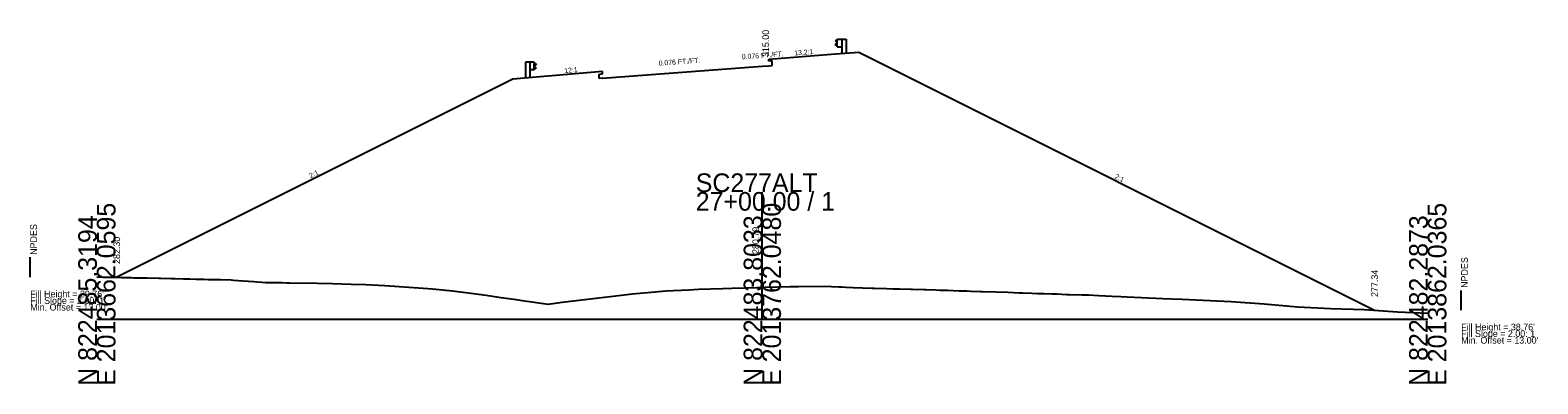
# Model space of a CAD drawing. Extents: x 205929 to 2357175, y -1785700 to 827636.
# Drawn here: x 2017410.1 to 2017636.7, y 825034.6 to 825087.7 of the extents above; entities that cross this region are included whole.
import ezdxf

# ---------------------------------------------------------------- set-up
doc = ezdxf.new("R2010")
doc.units = 0
for name, color, linetype in [('RD_GPK_XS_Cell', 7, 'Continuous'), ('RD_XS_Base', 7, 'Continuous'), ('RD_XS_EarthShd', 7, 'Continuous'), ('RD_XS_ExGround', 7, 'Continuous'), ('RD_XS_GR', 7, 'Continuous'), ('RD_XS_NPDES', 7, 'Continuous'), ('RD_XS_Pave', 7, 'Continuous'), ('RD_XS_TieSlope', 7, 'Continuous'), ('RD_XS_TX_Elev_EX', 7, 'Continuous'), ('RD_XS_TX_Elev_PR', 7, 'Continuous'), ('RD_XS_TX_ShdSlope', 7, 'Continuous'), ('RD_XS_TX_Slope', 7, 'Continuous'), ('RD_XS_TX_Warning', 7, 'Continuous')]:
    doc.layers.add(name, color=color, linetype=linetype)

msp = doc.modelspace()

# ---------------------------------------------------------------- linework, layer by layer
at = {"layer": 'RD_GPK_XS_Cell'}
for p, q in [((2017520.17, 825044.26), (2017520.17, 825063.36)), ((2017420.17, 825044.26), (2017520.17, 825044.26)), ((2017520.17, 825044.26), (2017620.17, 825044.26))]:
    msp.add_line(p, q, dxfattribs=at)
at = {"layer": 'RD_XS_Base'}
for p, q in [((2017496.17, 825080.44), (2017520.17, 825082.26)), ((2017520.17, 825082.26), (2017521.17, 825082.33))]:
    msp.add_line(p, q, dxfattribs=at)
at = {"layer": 'RD_XS_EarthShd'}
for p, q in [((2017521.17, 825083.33), (2017531.17, 825084.09)), ((2017531.17, 825084.09), (2017534.67, 825084.36)), ((2017496.17, 825081.44), (2017486.17, 825080.6)), ((2017486.17, 825080.6), (2017482.67, 825080.31))]:
    msp.add_line(p, q, dxfattribs=at)
at = {"layer": 'RD_XS_ExGround'}
msp.add_lwpolyline([(2017420.17, 825050.62), (2017421.07, 825050.6), (2017421.98, 825050.57), (2017423.24, 825050.56), (2017423.85, 825050.54), (2017425.4, 825050.51), (2017425.72, 825050.5), (2017427.72, 825050.46), (2017429.46, 825050.42), (2017429.77, 825050.41), (2017431.32, 825050.38), (2017431.95, 825050.36), (2017433.19, 825050.34), (2017434.13, 825050.32), (2017435.05, 825050.3), (2017436.32, 825050.27), (2017436.91, 825050.25), (2017438.77, 825050.21), (2017440.33, 825050.18), (2017440.7, 825050.15), (2017442.17, 825050.03), (2017442.98, 825049.97), (2017443.76, 825049.91), (2017445.55, 825049.8), (2017446.99, 825049.79), (2017448.02, 825049.78), (2017448.7, 825049.75), (2017449.18, 825049.75), (2017453.29, 825049.7), (2017455.6, 825049.62), (2017458.37, 825049.52), (2017460.6, 825049.46), (2017463.44, 825049.31), (2017465.6, 825049.17), (2017468.52, 825048.97), (2017470.6, 825048.81), (2017473.6, 825048.52), (2017475.6, 825048.29), (2017478.68, 825047.87), (2017480.6, 825047.58), (2017483.18, 825047.23), (2017484.06, 825047.1), (2017485.53, 825046.88), (2017487.98, 825046.52), (2017490.1, 825046.83), (2017495.6, 825047.48), (2017498.99, 825047.88), (2017500.6, 825048.06), (2017504.07, 825048.4), (2017505.6, 825048.51), (2017509.14, 825048.69), (2017510.6, 825048.78), (2017514.22, 825048.89), (2017515.6, 825048.93), (2017519.3, 825049.03), (2017520.17, 825049.05), (2017520.6, 825049.06), (2017524.38, 825049.17), (2017525.61, 825049.19), (2017529.45, 825049.21), (2017531.69, 825049.14), (2017532.08, 825049.12), (2017532.7, 825049.09), (2017533.83, 825049.04), (2017536.65, 825048.92), (2017537.01, 825048.91), (2017538.83, 825048.86), (2017539.85, 825048.85), (2017540.78, 825048.83), (2017542.44, 825048.8), (2017542.76, 825048.79), (2017544.47, 825048.74), (2017544.79, 825048.73), (2017546.23, 825048.67), (2017546.83, 825048.65), (2017547.98, 825048.61), (2017548.86, 825048.58), (2017549.75, 825048.55), (2017550.9, 825048.52), (2017551.5, 825048.5), (2017552.94, 825048.44), (2017553.26, 825048.43), (2017555.28, 825048.37), (2017557.13, 825048.31), (2017558.78, 825048.25), (2017559.33, 825048.23), (2017560.67, 825048.17), (2017561.51, 825048.15), (2017562.54, 825048.11), (2017563.69, 825048.09), (2017564.43, 825048.07), (2017565.88, 825048), (2017566.32, 825047.99), (2017568.21, 825047.94), (2017569.18, 825047.92), (2017570.72, 825047.84), (2017572.74, 825047.73), (2017574.07, 825047.68), (2017575.01, 825047.63), (2017580.36, 825047.38), (2017581.69, 825047.31), (2017583.28, 825047.26), (2017590.61, 825046.94), (2017595.61, 825046.56), (2017600.61, 825046.13), (2017605.61, 825045.89), (2017610.62, 825045.7), (2017615.62, 825045.36), (2017620.17, 825045.15)], dxfattribs=at)
at = {"layer": 'RD_XS_GR'}
for p, q in [((2017531.44, 825086.27), (2017531.17, 825086.07)), ((2017531.17, 825086.07), (2017531.17, 825086.02)), ((2017531.17, 825086.02), (2017531.44, 825085.82)), ((2017531.17, 825085.5), (2017531.44, 825085.7)), ((2017531.17, 825085.45), (2017531.17, 825085.5)), ((2017531.44, 825085.17), (2017531.44, 825086.34)), ((2017531.44, 825086.34), (2017532.11, 825086.34)), ((2017532.11, 825086.34), (2017532.11, 825084.16)), ((2017532.11, 825086.34), (2017532.78, 825086.34)), ((2017532.78, 825086.34), (2017532.78, 825084.21)), ((2017531.44, 825085.25), (2017531.17, 825085.45)), ((2017531.44, 825085.17), (2017532.11, 825085.17)), ((2017484.57, 825082.85), (2017484.57, 825080.47)), ((2017485.24, 825082.85), (2017484.57, 825082.85)), ((2017485.24, 825082.85), (2017485.24, 825080.53)), ((2017485.9, 825082.85), (2017485.24, 825082.85)), ((2017485.9, 825081.69), (2017485.24, 825081.69)), ((2017485.9, 825081.69), (2017485.9, 825082.85)), ((2017485.9, 825082.78), (2017486.17, 825082.58)), ((2017486.17, 825082.53), (2017485.9, 825082.33)), ((2017486.17, 825082.01), (2017485.9, 825082.21)), ((2017485.9, 825081.76), (2017486.17, 825081.96)), ((2017486.17, 825082.58), (2017486.17, 825082.53)), ((2017486.17, 825081.96), (2017486.17, 825082.01))]:
    msp.add_line(p, q, dxfattribs=at)
at = {"layer": 'RD_XS_NPDES'}
for p, q in [((2017410.16, 825050.56), (2017410.16, 825053.56)), ((2017625.19, 825045.6), (2017625.19, 825048.6))]:
    msp.add_line(p, q, dxfattribs=at)
at = {"layer": 'RD_XS_Pave'}
for p, q in [((2017521.17, 825083), (2017521.17, 825083.33)), ((2017495.67, 825081.07), (2017496.17, 825081.11)), ((2017495.67, 825080.4), (2017495.67, 825081.07)), ((2017496.17, 825081.11), (2017496.17, 825081.44)), ((2017521.67, 825083.04), (2017521.17, 825083)), ((2017521.17, 825082.33), (2017521.67, 825082.37)), ((2017521.67, 825082.37), (2017521.67, 825083.04)), ((2017496.17, 825080.44), (2017495.67, 825080.4))]:
    msp.add_line(p, q, dxfattribs=at)
at = {"layer": 'RD_XS_TieSlope'}
for p, q in [((2017534.67, 825084.36), (2017612.19, 825045.6)), ((2017482.67, 825080.31), (2017423.16, 825050.56))]:
    msp.add_line(p, q, dxfattribs=at)

# ---------------------------------------------------------------- texts
at = {"layer": 'RD_GPK_XS_Cell'}
for s, p in [('SC277ALT', (2017510.17, 825063.36)), ('27+00.00 / 1', (2017510.17, 825060.56))]:
    msp.add_text(s, height=2.8, dxfattribs=at).set_placement(p)
for s, p in [('E 2013662.0595', (2017422.97, 825034.26)), ('E 2013762.0480', (2017522.97, 825034.26)), ('E 2013862.0365', (2017622.97, 825034.26)), ('N 822485.3194', (2017420.17, 825034.26)), ('N 822483.8033', (2017520.17, 825034.26)), ('N 822482.2873', (2017620.17, 825034.26))]:
    msp.add_text(s, height=2.8, rotation=90, dxfattribs=at).set_placement(p)
at = {"layer": 'RD_XS_TX_Elev_EX'}
msp.add_text('280.79', height=1, rotation=90, dxfattribs=at).set_placement((2017519.67, 825054.05))
at = {"layer": 'RD_XS_TX_Elev_PR'}
for s, p in [(' 315.00', (2017521.17, 825083.26)), ('282.30', (2017423.66, 825052.56)), ('277.34', (2017612.69, 825047.6))]:
    msp.add_text(s, height=1, rotation=90, dxfattribs=at).set_placement(p)
at = {"layer": 'RD_XS_TX_ShdSlope'}
for s, rotation, p in [('13.2:1', 4.3347, (2017525, 825083.87)), ('12:1', 4.7636, (2017490.44, 825081.21))]:
    msp.add_text(s, height=0.75, rotation=rotation, dxfattribs=at).set_placement(p)
at = {"layer": 'RD_XS_TX_Slope'}
for s, rotation, p in [('0.076 FT./FT.', 4.3347, (2017504.62, 825082.33)), ('0.076 FT./FT.', 4.3347, (2017517.12, 825083.28)), ('2:1', 26.5651, (2017452.3, 825065.41)), ('2:1', 333.4349, (2017573.04, 825065.45))]:
    msp.add_text(s, height=0.75, rotation=rotation, dxfattribs=at).set_placement(p)
at = {"layer": 'RD_XS_TX_Warning'}
for p in [(2017411.16, 825053.56), (2017626.19, 825048.6)]:
    msp.add_text(' NPDES', height=1, rotation=90, dxfattribs=at).set_placement(p)
for s, p in [("Fill Height = 29.76' ", (2017410.16, 825047.56)), ('Fill Slope = 2.00: 1', (2017410.16, 825046.56)), ("Min. Offset = 13.00' ", (2017410.16, 825045.56)), ("Fill Height = 38.76' ", (2017625.19, 825042.6)), ('Fill Slope = 2.00: 1', (2017625.19, 825041.6)), ("Min. Offset = 13.00' ", (2017625.19, 825040.6))]:
    msp.add_text(s, height=1, dxfattribs=at).set_placement(p)

doc.saveas('drawing.dxf')
